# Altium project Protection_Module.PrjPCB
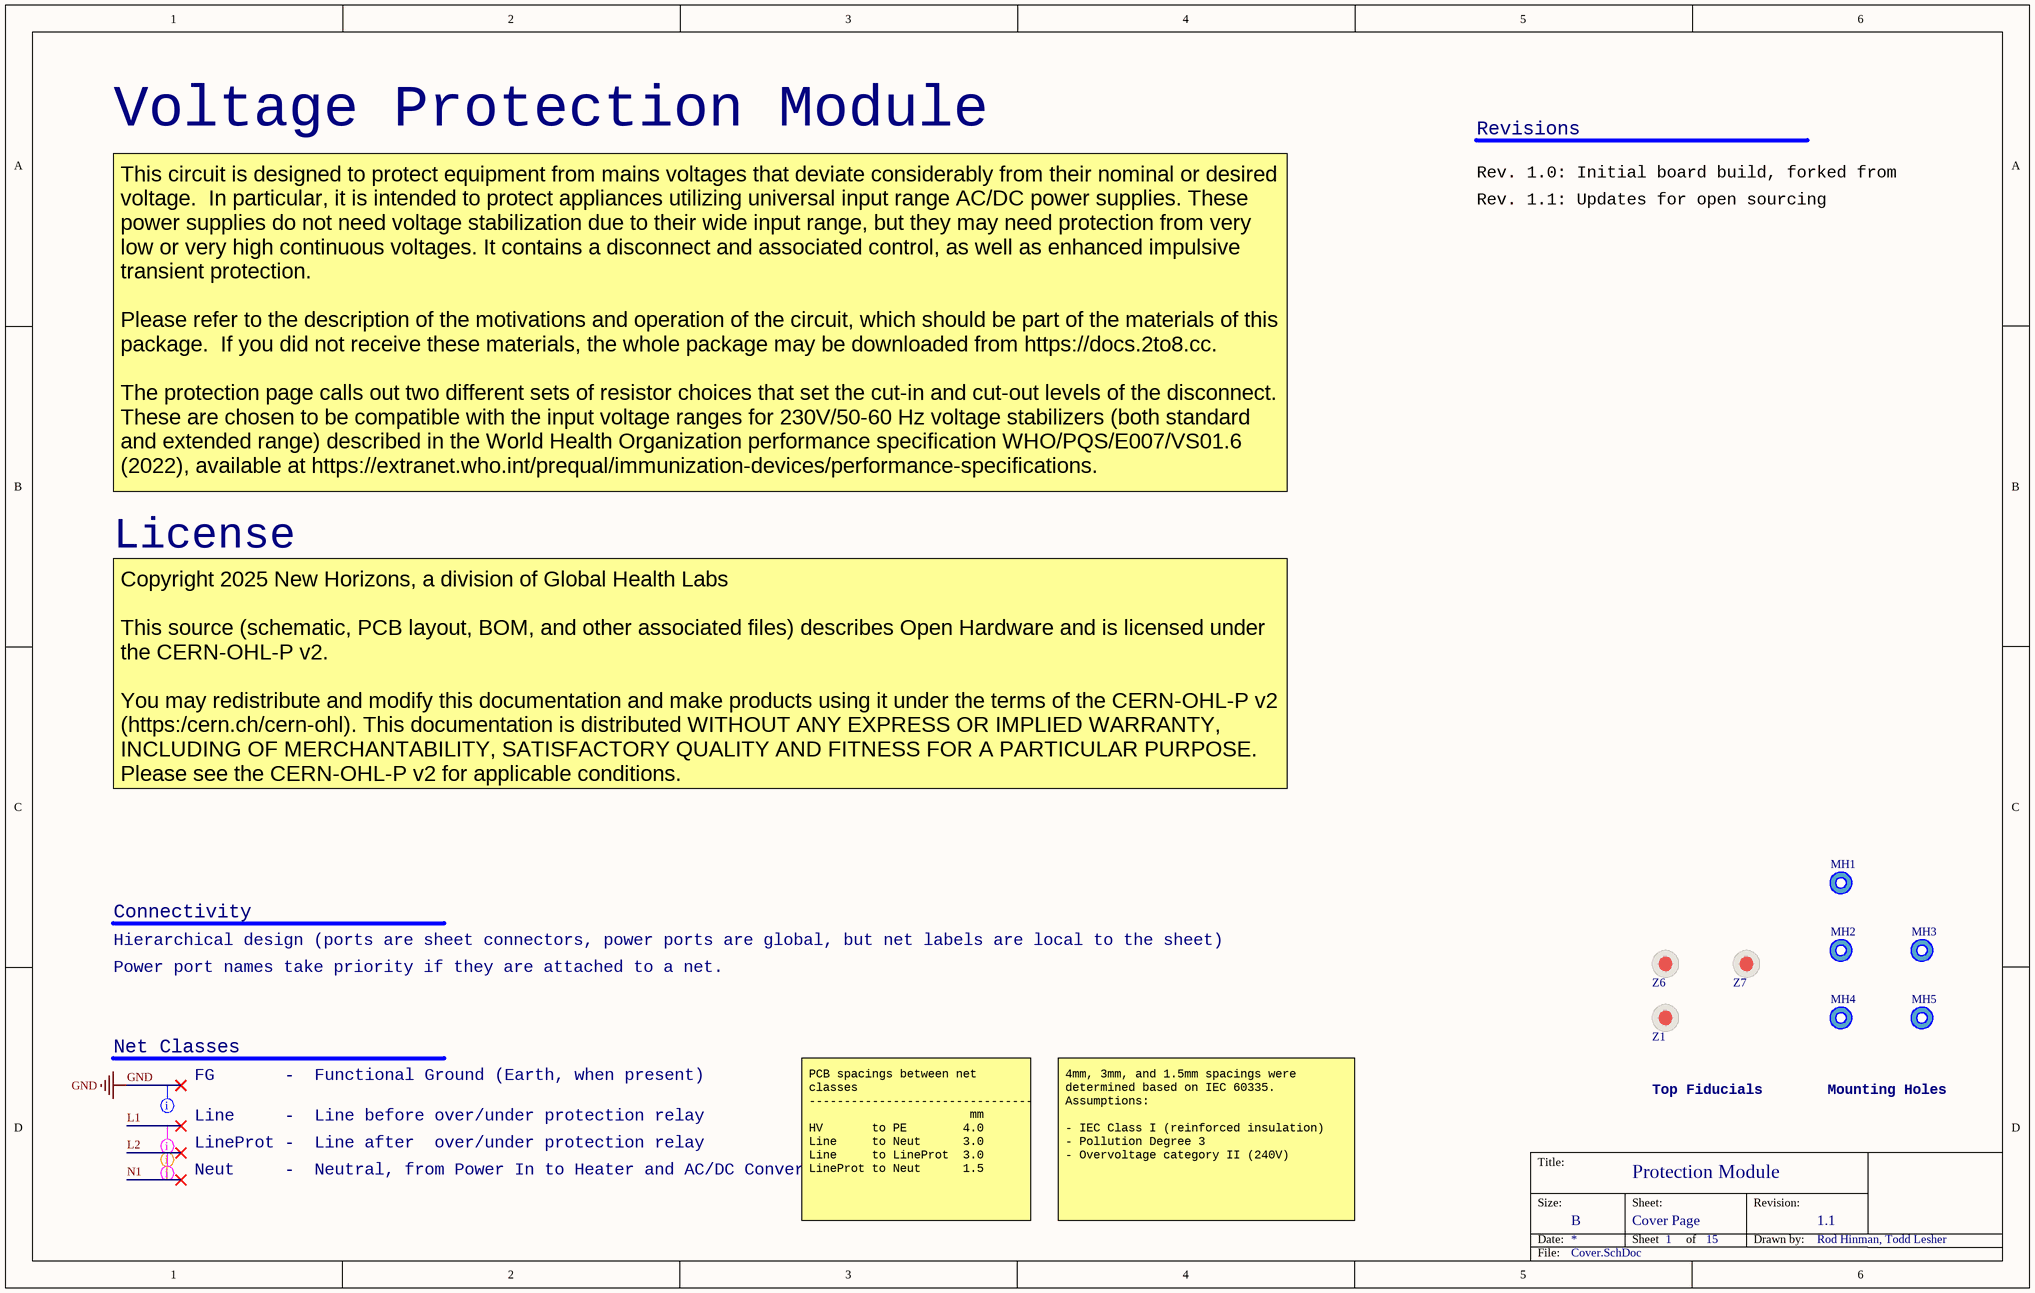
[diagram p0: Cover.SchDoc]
nhToday: 2025-05-24; nhSheetTotal: 3; nhProjRev: 1.1; nhProjName: Protection Module; nhEngPhone: 808-989-0977; nhEngName: Rod Hinman, Todd Lesher; nhEngEmail: rhinman@nhgh.org
3 sheets, 112 parts. Net scope: flat (ports and power ports of the same name join across sheets).
Board file: prot_mod.PcbDoc
Sheets:
  Cover.SchDoc
  PowerHV.SchDoc
  Protect.SchDoc

## Sheet Cover.SchDoc
size B; SheetNumber: 1; SheetTotal: 15; nhSheetName: Cover Page

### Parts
MH1  MOUNTING_HOLE_3MM_UNPLATED  [MOUNT_HOLE_3MM_NOCOPPER]  (value not drawn)  (no BOM)
MH2  MOUNTING_HOLE_3MM_UNPLATED  [MOUNT_HOLE_3MM_NOCOPPER]  (value not drawn)  (no BOM)
MH3  MOUNTING_HOLE_3MM_UNPLATED  [MOUNT_HOLE_3MM_NOCOPPER]  (value not drawn)  (no BOM)
MH4  MOUNTING_HOLE_3MM_UNPLATED  [MOUNT_HOLE_3MM_NOCOPPER]  (value not drawn)  (no BOM)
MH5  MOUNTING_HOLE_3MM_UNPLATED  [MOUNT_HOLE_3MM_NOCOPPER]  (value not drawn)  (no BOM)
Z1  FIDUCIAL_1_3  [FIDUCIAL_1_3_KEEPOUT]  (value not drawn)  (no BOM)
Z6  FIDUCIAL_1_3  [FIDUCIAL_1_3_KEEPOUT]  (value not drawn)  (no BOM)
Z7  FIDUCIAL_1_3  [FIDUCIAL_1_3_KEEPOUT]  (value not drawn)  (no BOM)

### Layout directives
net class Neut: N1
net class Line: L1
net class LineProt: L2
net class FG: GND

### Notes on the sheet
- Voltage Protection Module
- Revisions
- Rev. 1.0: Initial board build, forked from Protection-1
- Rev. 1.1: Updates for open sourcing
- This circuit is designed to protect equipment from mains voltages that deviate considerably from their nominal or desired voltage.  In particular, it is intended to protect appliances utilizing universal input range AC/DC power supplies. These power supplies do not need voltage stabilization due to their wide input range, but they may need protection from very low or very high continuous voltages. It contains a disconnect and associated control, as well as enhanced impulsive transient protection.
  Please refer to the description of the motivations and operation of the circuit, which should be part of the materials of this package.  If you did not receive these materials, the whole package may be downloaded from https://docs.2to8.cc.
  The protection page calls out two different sets of resistor choices that set the cut-in and cut-out levels of the disconnect.  These are chosen to be compatible with the input voltage ranges for 230V/50-60 Hz voltage stabilizers (both standard and extended range) described in the World Health Organization performance specification WHO/PQS/E007/VS01.6 (2022), available at https://extranet.who.int/prequal/immunization-devices/performance-specifications.
- License
- Copyright 2025 New Horizons, a division of Global Health Labs
  This source (schematic, PCB layout, BOM, and other associated files) describes Open Hardware and is licensed under the CERN-OHL-P v2.
  You may redistribute and modify this documentation and make products using it under the terms of the CERN-OHL-P v2 (https:/cern.ch/cern-ohl). This documentation is distributed WITHOUT ANY EXPRESS OR IMPLIED WARRANTY, INCLUDING OF MERCHANTABILITY, SATISFACTORY QUALITY AND FITNESS FOR A PARTICULAR PURPOSE. Please see the CERN-OHL-P v2 for applicable conditions.
- Hierarchical design (ports are sheet connectors, power ports are global, but net labels are local to the sheet)
- Power port names take priority if they are attached to a net.
- Connectivity
- Net Classes
- FG       -  Functional Ground (Earth, when present)
- Top Fiducials
- Mounting Holes
- Neut     -  Neutral, from Power In to Heater and AC/DC Converter
- Line     -  Line before over/under protection relay
- LineProt -  Line after  over/under protection relay
- PCB spacings between net classes
  --------------------------------
  mm
  HV       to PE        4.0
  Line     to Neut      3.0
  Line     to LineProt  3.0
  LineProt to Neut      1.5
- 4mm, 3mm, and 1.5mm spacings were determined based on IEC 60335.
  Assumptions:
  - IEC Class I (reinforced insulation)
  - Pollution Degree 3
  - Overvoltage category II (240V)

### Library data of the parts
MH1-MH5 = CMP-NOBOM-00004-1: Hole for M3 screw, unplated
Z1 Z6 Z7 = CMP-NOBOM-00000-1: Fiducial 1 mm copper, 3 mm solder mask, two footprint options.

## Sheet PowerHV.SchDoc
size B; SheetNumber: 2; SheetTotal: 15; nhSheetName: HV Power
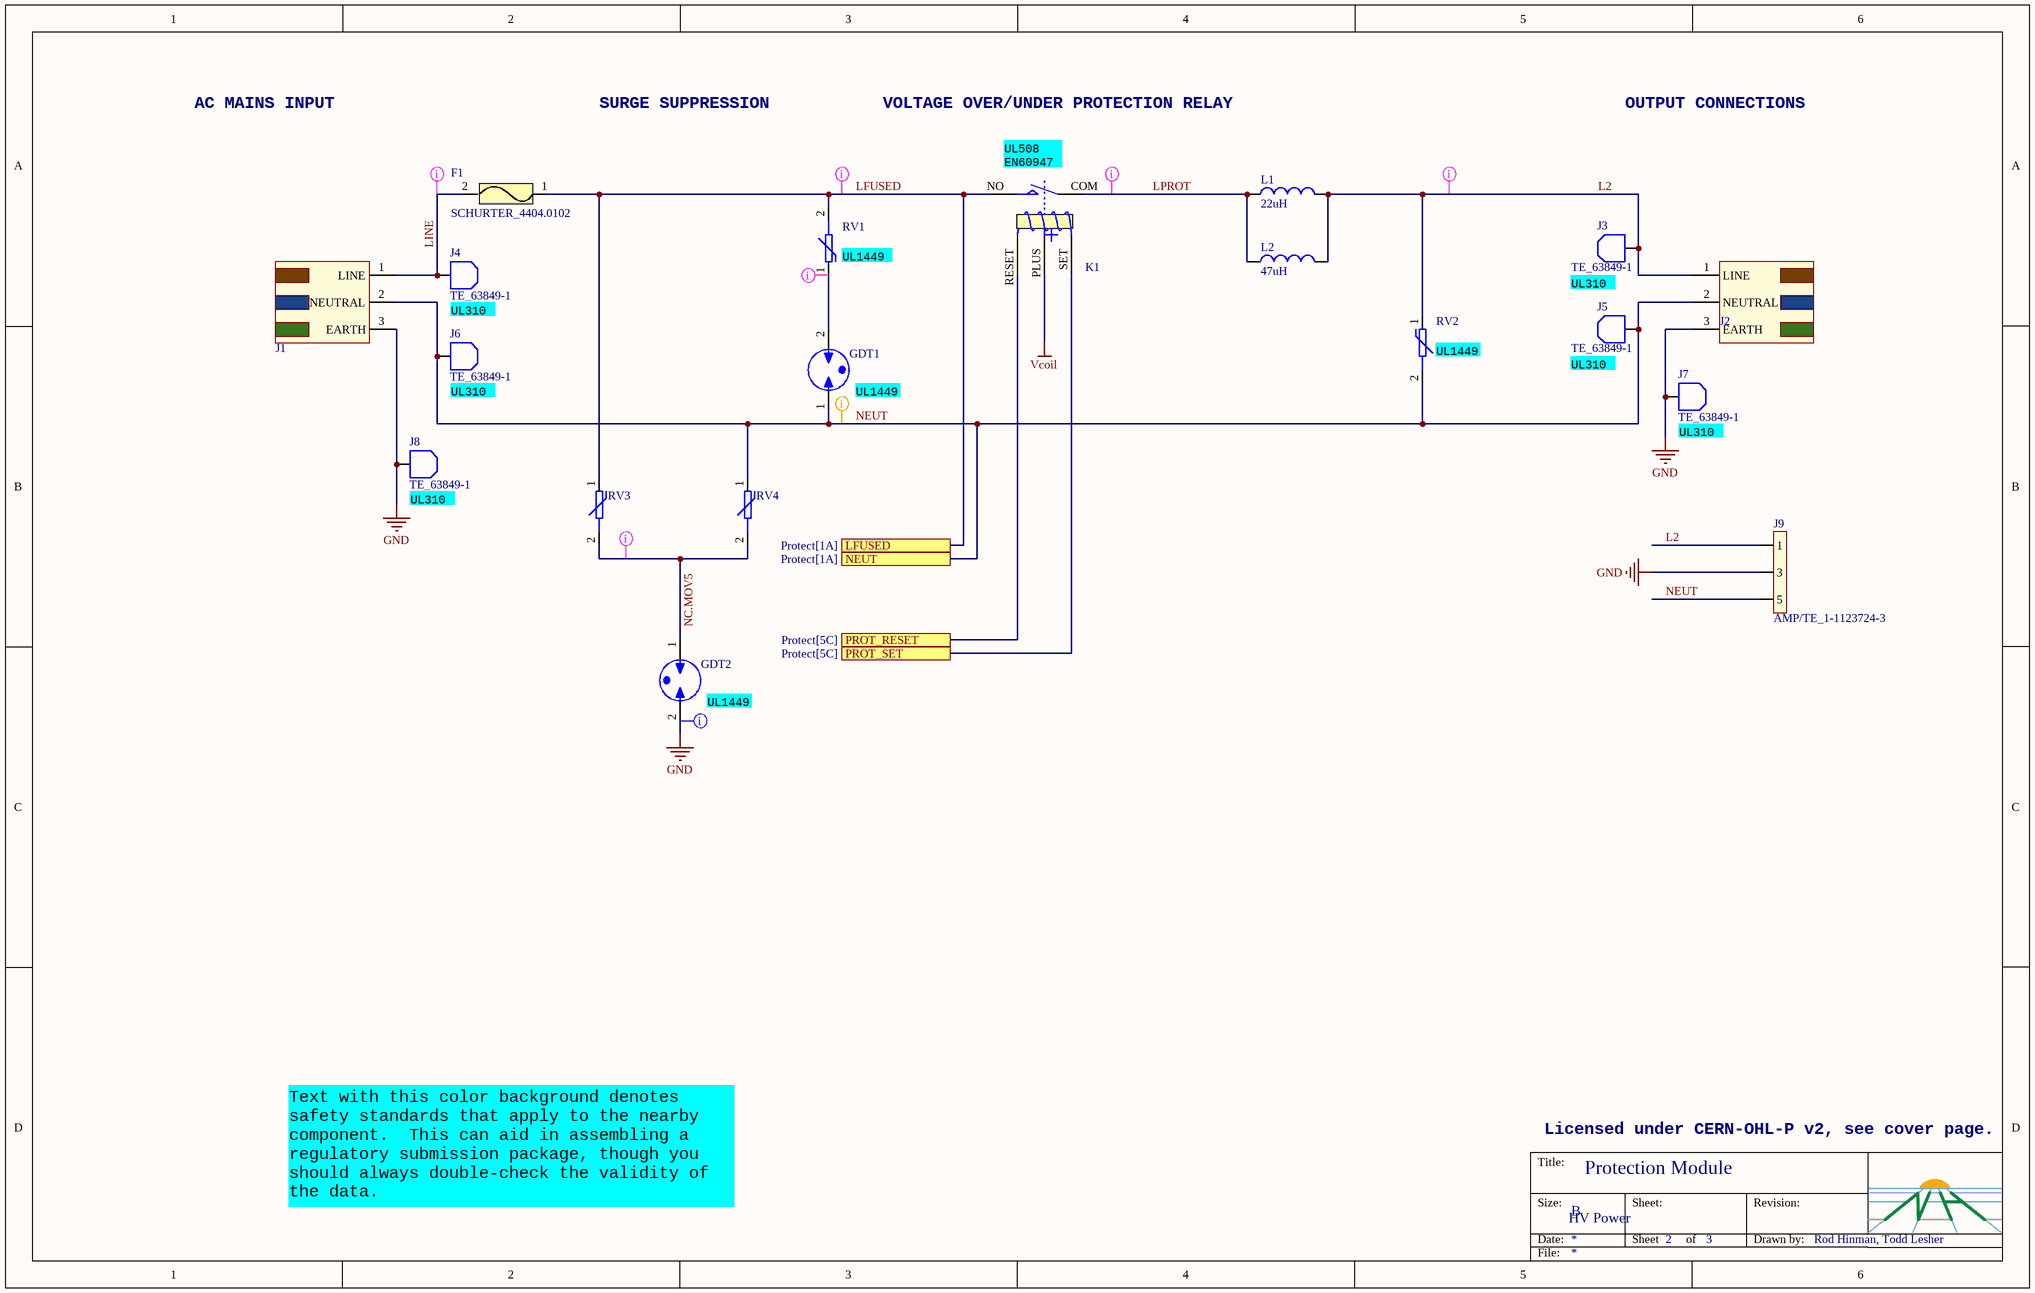
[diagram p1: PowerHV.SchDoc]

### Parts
F1  SCHURTER_4404.0102  [SCHURTER_T9-818]
GDT1  CG31.0L  [LITTELFUSE_CG3x]  (value not drawn)
GDT2  CG32.5L  [LITTELFUSE_CG3x]  (value not drawn)
J1  703W-00/54  [QUALTEK_703W-00/54]  (value not drawn)
J2  PX0675/PC  [BULGIN_PX0675/PC]  (value not drawn)
J3  TE_63849-1  [AMP_63849-1]
J4  TE_63849-1  [AMP_63849-1]
J5  TE_63849-1  [AMP_63849-1]
J6  TE_63849-1  [AMP_63849-1]
J7  TE_63849-1  [AMP_63849-1]
J8  TE_63849-1  [AMP_63849-1]
J9  AMP/TE_1-1123724-3  [AMP_1-1123724-3]
K1  TE_CONN_2-1415898-5  [TE_RT1_2COIL_LATCHING]  (value not drawn)
L1  value 22uH  [INDUCTOR-BOURNS_SRP1265CC]  (hidden comment: SRP1265CC-220M)
L2  value 47uH  [BELFUSE_HCTI_TOROIDAL_INDUCTOR]  (hidden comment: BELFUSE_HCTI-47-10.7)
RV1  TMOV20RP300E  [MOV_RAD7.5P5.5S_DISC_20X11.5]  (value not drawn)
RV2  TMOV20RP300E  [MOV_RAD7.5P5.5S_DISC_20X11.5]  (value not drawn)
RV3  TMOV20RP300E  [MOV_RAD7.5P5.5S_DISC_20X11.5]  (value not drawn)
RV4  TMOV20RP300E  [MOV_RAD7.5P5.5S_DISC_20X11.5]  (value not drawn)

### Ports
LFUSED (see Protect[1A]), NEUT (see Protect[1A]), PROT_RESET (see Protect[5C]), PROT_SET (see Protect[5C])

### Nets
GND: GDT2.2 J1.3(EARTH) J2.3(EARTH) J7.1 J8.1 J9.3
Vcoil: K1.PLUS
L2: J2.1(LINE) J3.1 J9.1 L1.2 L2.2 RV2.1
LFUSED: F1.1 K1.NO RV1.2 RV3.1 ; port LFUSED
LINE: F1.2 J1.1(LINE) J4.1
LPROT: K1.COM L1.1 L2.1
NC.MOV5: GDT2.1 RV3.2 RV4.2
NEUT: GDT1.1 J1.2(NEUTRAL) J2.2(NEUTRAL) J5.1 J6.1 J9.5 RV2.2 RV4.1 ; port NEUT
PROT_RESET: K1.RESET ; port PROT_RESET
PROT_SET: K1.SET ; port PROT_SET
NetGDT1_2: GDT1.2 RV1.1

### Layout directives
net class Line: LFUSED, LINE, NC.MOV5, NetGDT1_2
net class LineProt: L2, LPROT
net class Neut: NEUT
net class FG: GND

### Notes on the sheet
- AC MAINS INPUT
- SURGE SUPPRESSION
- VOLTAGE OVER/UNDER PROTECTION RELAY
- (near K1) UL508
  EN60947
- OUTPUT CONNECTIONS
- (near RV1) UL1449
- UL310
- (near RV2) UL1449
- (near J5) UL310
- (near J6) UL310
- (near GDT1) UL1449
- (near J7) UL310
- (near J8) UL310
- (near GDT2) UL1449
- Licensed under CERN-OHL-P v2, see cover page.
- Text with this color background denotes safety standards that apply to the nearby component.  This can aid in assembling a regulatory submission package, though you should always double-check the validity of the data.

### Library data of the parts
F1 = CMP-FUSE-00000-2: Circuit Breaker Thermal 1P 240VAC/48DC 10A PCB Mnt-Thru-Hole Push Reset QC Term.; Voltage Rating (AC): 240V; Voltage Rating (DC): 48V
GDT1 = CMP-PROT-00004-1: CG3 Series - Two Terminal High Voltage Gas Plasma Arresters, 1000V, 10kA, plug in, RoHS; Breakdown Voltage: 1.0kV
GDT2 = CMP-PROT-00003-2: Arrestor; 2500 V (min.) (breakdown); Rugged Ceramic-metal Package; 1 Pf (max.); Breakdown Voltage: 2.5kV
J1 = CMP-CONN-00000-2: Conn Electrical Power Inlet Right Angled Pin Cont 3 Cond 3 Poles Solder 250V
J2 = CMP-CONN-00001-2: Conn Electrical Power Outlet Right Angled Pin Cont 3 Cond 3 Poles Solder 250V
J3-J8 = CMP-CONN-00004-1: Quick Disconnect Terminal 12-24AWG Brass Tab 14.02mm Tin Over Copper/Tin Over Nickel Bag; Tab Width: 6.35mm
J9 = CMP-CONN-00006-1: Conn Power HDR 5 POS 3.96mm Solder ST Thru-Hole 5 Terminal 1 Port; Voltage Rating: 250V
K1 = CMP-RELAY-00000-2: Electromechanical Relay SPST-NO 16A 12VDC 240Ohm Through Hole; Contact Voltage Rating (AC): 250V; Coil Power: 600mW; Throw Configuration: SPST
L1 = CMP-IND-00003-1: Inductor Power Shielded Wirewound 22uH 20% 100KHz 20Q-Factor Carbonyl Powder 10A 0.037Ohm DCR
L2 = CMP-IND-00005-2: 47 µH Shielded Toroidal Inductor 10.7 A 16mOhm Max Radial, Vertical (Open); Tolerance: 15%; DC Resistance (DCR): 16mR; Core Material: Ferrite; Current Rating: 10.7A
RV1 RV3 RV4 = CMP-PROT-00005-2: Thermally Protected Varistor 300 V RMS 775 V Clamp 10000 A 800 pF Radial Lead; Voltage Rating (AC): 300V; Varistor Voltage: 517V
RV2 = CMP-PROT-00005-2: Thermally Protected Varistor 300 V RMS 775 V Clamp 10000 A 800 pF Radial Lead; Varistor Voltage: 517V; Voltage Rating (AC): 300V

## Sheet Protect.SchDoc
size B; SheetNumber: 4; SheetTotal: 15; nhSheetName: Protect
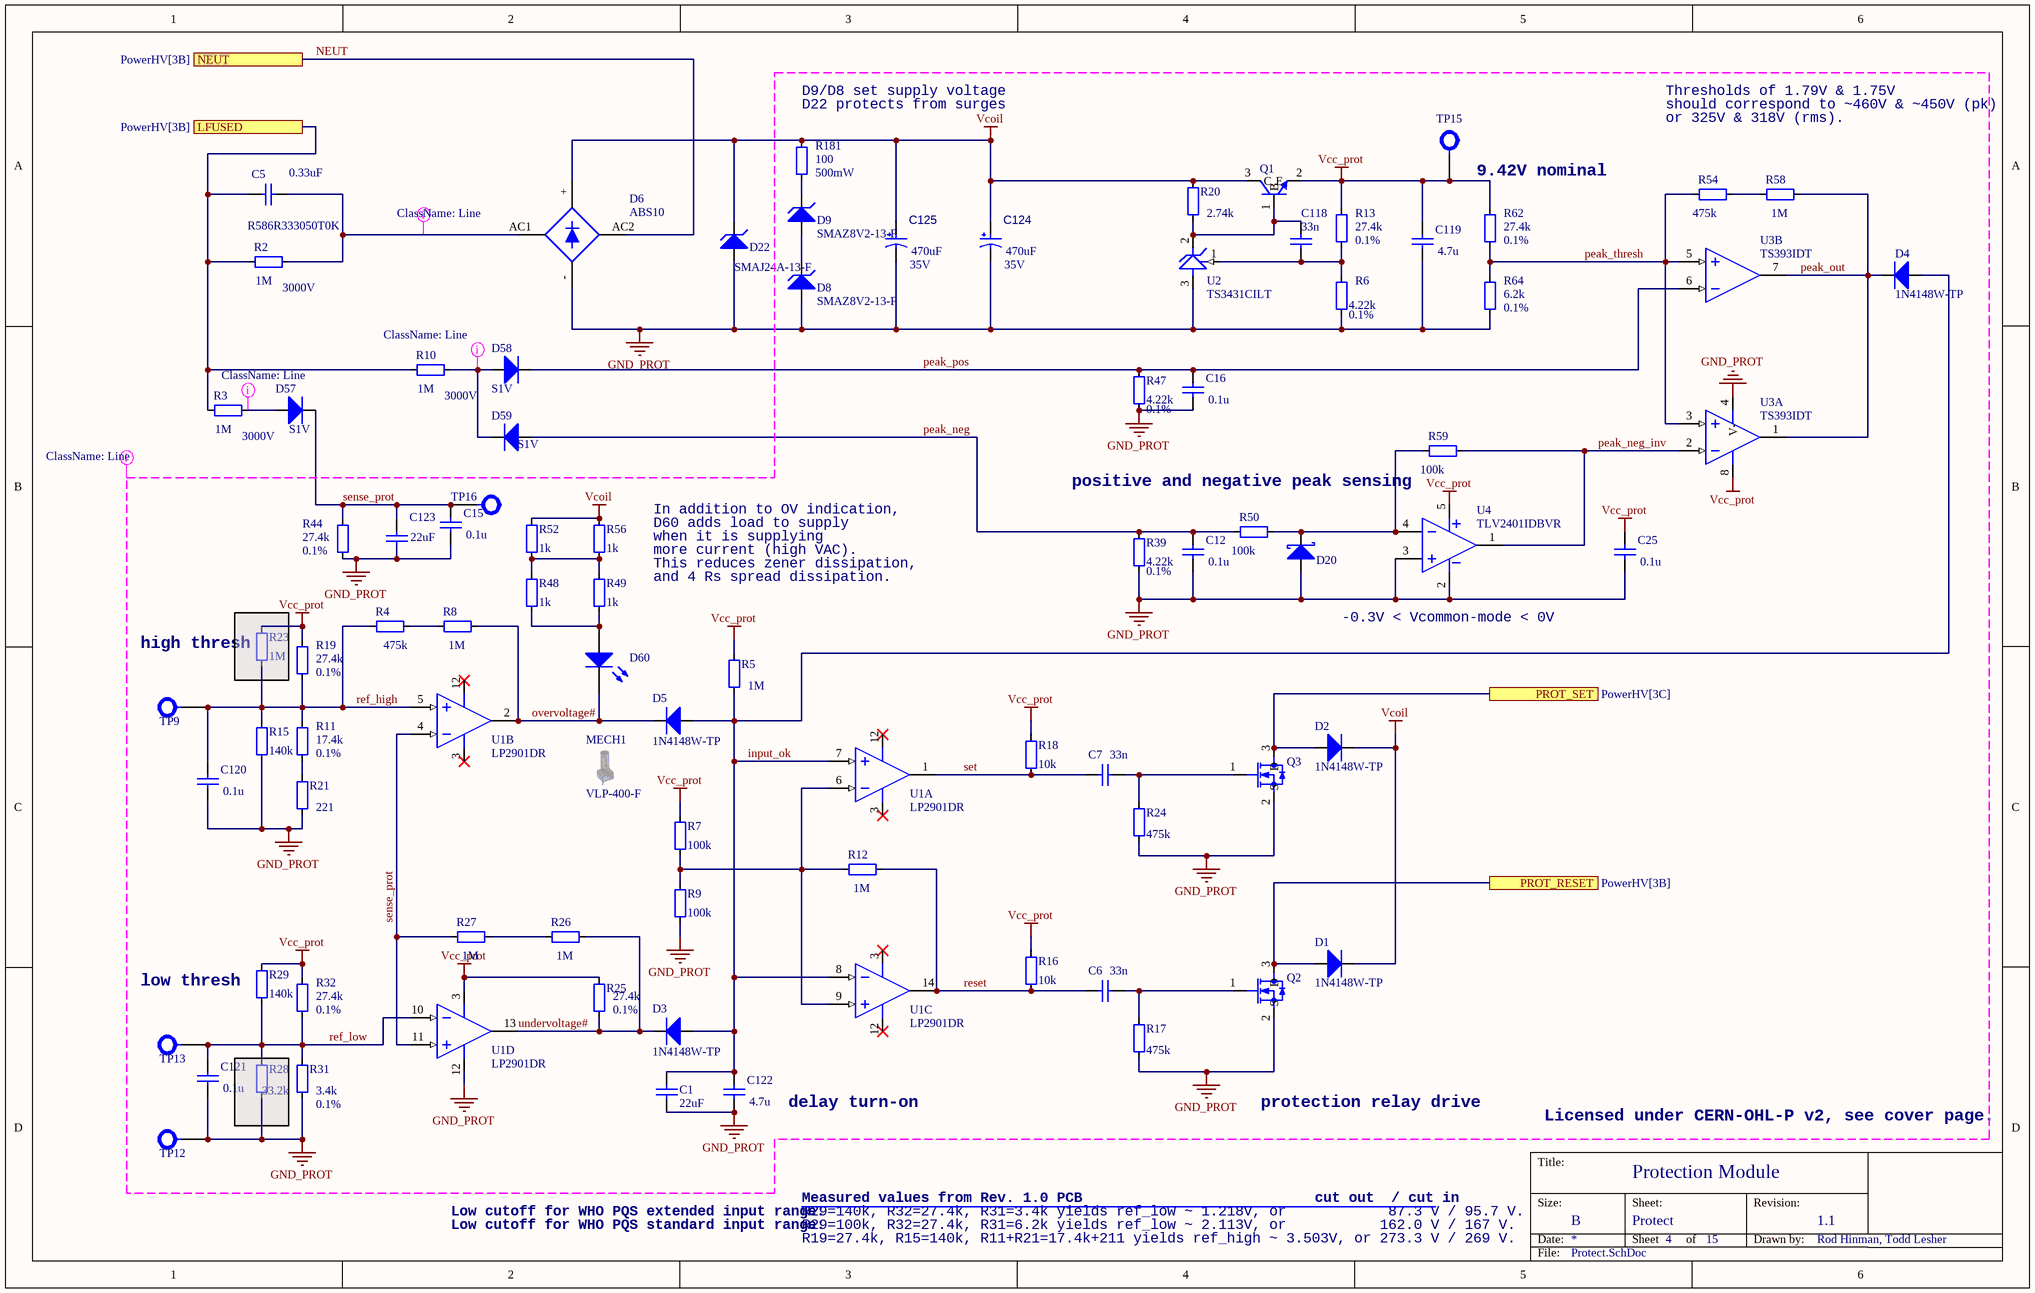
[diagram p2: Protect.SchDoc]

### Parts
C1  value 22uF  [CAPC2012X135,0805,]  (hidden comment: CL21A226MOCLRNC)
C5  R586R333050T0K  value 0.33uF  [CAP_RAD28P3213X22]
C6  value 33n  [CAPC1608X09N[0603]]  (hidden comment: CL10B333KB8NNNC)
C7  value 33n  [CAPC1608X09N[0603]]  (hidden comment: CL10B333KB8NNNC)
C12  value 0.1u  [CAPC1608X09N[0603]]  (hidden comment: CL10B104KB8NNNL)
C15  value 0.1u  [CAPC1608X09N[0603]]  (hidden comment: CL10B104KB8NNNL)
C16  value 0.1u  [CAPC1608X09N[0603]]  (hidden comment: CL10B104KB8NNNL)
C25  value 0.1u  [CAPC1608X09N[0603]]  (hidden comment: CL10B104KB8NNNL)
C118  value 33n  [CAPC1608X09N[0603]]  (hidden comment: CL10B333KB8NNNC)
C119  value 4.7u  [CAPC1608X09N[0603]]  (hidden comment: CL10A475KA8NQNC)
C120  value 0.1u  [CAPC1608X09N[0603]]  (hidden comment: CL10B104KB8NNNL)
C121  value 0.1u  [CAPC1608X09N[0603]]  (hidden comment: CL10B104KB8NNNL)
C122  value 4.7u  [CAPC1608X09N[0603]]  (hidden comment: CL10A475KA8NQNC)
C123  value 22uF  [CAPC2012X135,0805,]  (hidden comment: CL21A226MOCLRNC)
C124  value 470uF  Voltage Rating (DC): 35V  [CAP_RAD5P_CYL_10X20]  (hidden comment: ESH477M035AH3AA)
C125  value 470uF  Voltage Rating (DC): 35V  [CAP_RAD5P_CYL_10X20]  (hidden comment: ESH477M035AH3AA)
D1  1N4148W-TP  [SOD-123]
D2  1N4148W-TP  [SOD-123]
D3  1N4148W-TP  [SOD-123]
D4  1N4148W-TP  [SOD-123]
D5  1N4148W-TP  [SOD-123]
D6  ABS10  [SOP400P640X170-4N_BRIDGE]
D8  SMAZ8V2-13-F  [DO-214AC]
D9  SMAZ8V2-13-F  [DO-214AC]
D20  MBR130T1G  [SOD-123]  (value not drawn)
D22  SMAJ24A-13-F  [DO-214AC]
D57  S1V  [DO-214AC]
D58  S1V  [DO-214AC]
D59  S1V  [DO-214AC]
D60  APTR3216SURCK  [LEDC3216X08NREDBOT,1206,]  (value not drawn)
MECH1  VLP-400-F  [BIVAR_VLP-400-F]
Q1  BCV72,215  [SOT95P275X125-3N]  (value not drawn)
Q2  IRLML6346TRPBF  [SOT95P275X125-3N]  (value not drawn)
Q3  IRLML6346TRPBF  [SOT95P275X125-3N]  (value not drawn)
R2  value 1M  Voltage Rating: 3000V  [RESC6534X70,2512,]  (hidden comment: CHV2512-FX-1004ELF)
R3  value 1M  Voltage Rating: 3000V  [RESC6534X70,2512,]  (hidden comment: CHV2512-FX-1004ELF)
R4  value 475k  [RESC1608X05AN[0603]]  (hidden comment: ERJ-3EKF4753V)
R5  value 1M  [RESC1608X05AN[0603]]  (hidden comment: ERJ-3EKF1004V)
R6  value 4.22k  Tolerance: 0.1%  [RESC1608X05AN[0603]]  (hidden comment: ERA-3AEB4221V)
R7  value 100k  [RESC1608X05AN[0603]]  (hidden comment: ERJ-3EKF1003V)
R8  value 1M  [RESC1608X05AN[0603]]  (hidden comment: ERJ-3EKF1004V)
R9  value 100k  [RESC1608X05AN[0603]]  (hidden comment: ERJ-3EKF1003V)
R10  value 1M  Voltage Rating: 3000V  [RESC6534X70,2512,]  (hidden comment: CHV2512-FX-1004ELF)
R11  value 17.4k  Tolerance: 0.1%  [RESC1608X05AN[0603]]  (hidden comment: ERA-3AEB1742V)
R12  value 1M  [RESC1608X05AN[0603]]  (hidden comment: ERJ-3EKF1004V)
R13  value 27.4k  Tolerance: 0.1%  [RESC1608X05AN[0603]]  (hidden comment: ERA-3AEB2742V)
R15  value 140k  [RESC1608X05AN[0603]]  (hidden comment: RMCF0603FT140K)
R16  value 10k  [RESC1608X05AN[0603]]  (hidden comment: RMCF0603FT10K0)
R17  value 475k  [RESC1608X05AN[0603]]  (hidden comment: ERJ-3EKF4753V)
R18  value 10k  [RESC1608X05AN[0603]]  (hidden comment: RMCF0603FT10K0)
R19  value 27.4k  Tolerance: 0.1%  [RESC1608X05AN[0603]]  (hidden comment: ERA-3AEB2742V)
R20  value 2.74k  [RESC1608X05AN[0603]]  (hidden comment: RMCF0603FT2K74)
R21  value 221  [RESC1608X05AN[0603]]  (hidden comment: ERJ-3EKF2210V)
R23  value 1M  [RESC1608X05AN[0603]]  (hidden comment: ERJ-3EKF1004V)
R24  value 475k  [RESC1608X05AN[0603]]  (hidden comment: ERJ-3EKF4753V)
R25  value 27.4k  Tolerance: 0.1%  [RESC1608X05AN[0603]]  (hidden comment: ERA-3AEB2742V)
R26  value 1M  [RESC1608X05AN[0603]]  (hidden comment: ERJ-3EKF1004V)
R27  value 1M  [RESC1608X05AN[0603]]  (hidden comment: ERJ-3EKF1004V)
R28  value 33.2k  [RESC1608X05AN[0603]]  (hidden comment: ERJ-3EKF3322V)
R29  value 140k  [RESC1608X05AN[0603]]  (hidden comment: RMCF0603FT140K)
R31  value 3.4k  Tolerance: 0.1%  [RESC1608X05AN[0603]]  (hidden comment: ERA-3AEB3401V)
R32  value 27.4k  Tolerance: 0.1%  [RESC1608X05AN[0603]]  (hidden comment: ERA-3AEB2742V)
R39  value 4.22k  Tolerance: 0.1%  [RESC1608X05AN[0603]]  (hidden comment: ERA-3AEB4221V)
R44  value 27.4k  Tolerance: 0.1%  [RESC1608X05AN[0603]]  (hidden comment: ERA-3AEB2742V)
R47  value 4.22k  Tolerance: 0.1%  [RESC1608X05AN[0603]]  (hidden comment: ERA-3AEB4221V)
R48  value 1k  [RESC1608X05AN[0603]]  (hidden comment: ERJ-3EKF1001V)
R49  value 1k  [RESC1608X05AN[0603]]  (hidden comment: ERJ-3EKF1001V)
R50  value 100k  [RESC1608X05AN[0603]]  (hidden comment: ERJ-3EKF1003V)
R52  value 1k  [RESC1608X05AN[0603]]  (hidden comment: ERJ-3EKF1001V)
R54  value 475k  [RESC1608X05AN[0603]]  (hidden comment: ERJ-3EKF4753V)
R56  value 1k  [RESC1608X05AN[0603]]  (hidden comment: ERJ-3EKF1001V)
R58  value 1M  [RESC1608X05AN[0603]]  (hidden comment: ERJ-3EKF1004V)
R59  value 100k  [RESC1608X05AN[0603]]  (hidden comment: ERJ-3EKF1003V)
R62  value 27.4k  Tolerance: 0.1%  [RESC1608X05AN[0603]]  (hidden comment: ERA-3AEB2742V)
R64  value 6.2k  Tolerance: 0.1%  [RESC1608X05AN[0603]]  (hidden comment: ERA-3AEB622V)
R181  value 100  Power: 500mW  [RESC2012X06N,0805,]  (hidden comment: ERJ-P06F1000V)
TP9  TP TH  0.78mm  [TP_TH078H127P]  (value not drawn)  (no BOM)
TP12  TP TH  0.78mm  [TP_TH078H127P]  (value not drawn)  (no BOM)
TP13  TP TH  0.78mm  [TP_TH078H127P]  (value not drawn)  (no BOM)
TP15  TP TH  0.78mm  [TP_TH078H127P]  (value not drawn)  (no BOM)
TP16  TP TH  0.78mm  [TP_TH078H127P]  (value not drawn)  (no BOM)
U1  LP2901DR  [SOIC127P600X175-14N]  (parts A,B,C,D of 4)
U2  TS3431CILT  [SOT95P275X125-3N]
U3  TS393IDT  [SOIC127P600X175-8N]  (parts A,B of 2)
U4  TLV2401IDBVR  [SOT95P280X145-5N]

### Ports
LFUSED (see PowerHV[3B]), NEUT (see PowerHV[3B]), PROT_RESET (see PowerHV[3B]), PROT_SET (see PowerHV[3C])

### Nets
GND_PROT: C1.2 C12.2 C15.2 C16.2 C25.2 C119.2 C120.2 C121.2 C122.2 C123.2 C124.- C125.- D6.- D8.A D20.A D22.A Q2.2(S) Q3.2(S) R6.2 R9.2 R15.2 R17.1 R21.2 R24.1 R28.2 R31.2 R39.2 R44.2 R47.2 R64.2 TP12.1 U1.12(V-) U2.3(A) U3.4(V-) U4.2(-Vs) U4.3(+IN)
Vcc_prot: C25.1 C119.1 Q1.2(E) R5.1 R7.1 R13.1 R16.1 R18.1 R19.1 R23.1 R25.2 R29.1 R32.1 R62.1 TP15.1 U1.3(V+) U3.8(V+) U4.5(+Vs)
Vcoil: C124.+ C125.+ D1.K D2.K D6.+ D22.K Q1.3(C) R20.2 R52.1 R56.1 R181.1
input_ok: C1.1 C122.1 D3.A D4.A D5.A R5.2 U1.7(IN1+) U1.8(IN3-)
LFUSED: C5.1 R2.1 R3.1 R10.1 ; port LFUSED
NEUT: D6.AC2 ; port NEUT
overvoltage#: D5.K D60.K R8.2 U1.2(OUT2)
peak_neg: C12.1 D59.A R39.1 R50.1
peak_neg_inv: R59.2 U3.2(IN1-) U4.1(OUT)
peak_out: D4.K R58.2 U3.1(OUT1) U3.7(OUT2)
peak_pos: C16.1 D58.K R47.1 U3.6(IN2-)
peak_thresh: R54.2 R62.2 R64.1 U3.3(IN1+) U3.5(IN2+)
PROT_RESET: D1.A Q2.3(D) ; port PROT_RESET
PROT_SET: D2.A Q3.3(D) ; port PROT_SET
ref_high: C120.1 R4.2 R11.2 R15.1 R19.2 R23.2 TP9.1 U1.5(IN2+)
ref_low: C121.1 R28.1 R29.2 R31.1 R32.2 TP13.1 U1.10(IN4-)
reset: C6.1 R12.2 R16.2 U1.14(OUT3)
sense_prot: C15.1 C123.1 D57.K R27.1 R44.1 TP16.1 U1.4(IN2-) U1.11(IN4+)
set: C7.1 R18.2 U1.1(OUT1)
undervoltage#: D3.K R25.1 R26.2 U1.13(OUT4)
NetC5_2: C5.2 D6.AC1 R2.2
NetC6_2: C6.2 Q2.1(G) R17.2
NetC7_2: C7.2 Q3.1(G) R24.2
NetC118_1: C118.1 Q1.1(B) R20.1 U2.2(K)
NetC118_2: C118.2 R6.1 R13.2 U2.1(VREF)
NetD8_K: D8.K D9.A
NetD9_K: D9.K R181.2
NetD20_K: D20.K R50.2 R59.1 U4.4(-IN)
NetD57_A: D57.A R3.2
NetD58_A: D58.A D59.K R10.2
NetD60_A: D60.A R48.2 R49.2
NetR4_1: R4.1 R8.1
NetR7_2: R7.2 R9.1 R12.1 U1.6(IN1-) U1.9(IN3+)
NetR11_1: R11.1 R21.1
NetR26_1: R26.1 R27.2
NetR48_1: R48.1 R49.1 R52.2 R56.2
NetR54_1: R54.1 R58.1

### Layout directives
net class Line: GND_PROT, input_ok, NetC5_2, NetD57_A, NetD58_A, overvoltage#, peak_neg, peak_neg_inv, peak_out, peak_pos, peak_thresh, ref_high, ref_low, reset, sense_prot, set, undervoltage#, Vcc_prot, Vcoil

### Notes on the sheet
- (near R181) D9/D8 set supply voltage
- Thresholds of 1.79V & 1.75V
- (near R181) D22 protects from surges
- should correspond to ~460V & ~450V (pk)
- or 325V & 318V (rms).
- 9.42V nominal
- positive and negative peak sensing
- D60 adds load to supply
- when it is supplying
- more current (high VAC).
- This reduces zener dissipation,
- In addition to OV indication,
- and 4 Rs spread dissipation.
- (near U4) -0.3V < Vcommon-mode < 0V
- (near R23) high thresh
- low thresh
- delay turn-on
- protection relay drive
- Licensed under CERN-OHL-P v2, see cover page.
- Low cutoff for WHO PQS extended input range:
- Low cutoff for WHO PQS standard input range:
- R29=140k, R32=27.4k, R31=3.4k yields ref_low ~ 1.218V, or            87.3 V / 95.7 V.
- R19=27.4k, R15=140k, R11+R21=17.4k+211 yields ref_high ~ 3.503V, or 273.3 V / 269 V.
- Measured values from Rev. 1.0 PCB
- R29=100k, R32=27.4k, R31=6.2k yields ref_low ~ 2.113V, or           162.0 V / 167 V.
- cut out  / cut in

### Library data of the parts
C1 C123 = CMP-CAP-00014-1: Multilayer Ceramic Capacitor, 22 uF, 16 V, ± 20%, X5R, 0805 [2012 Metric]; Voltage: 16V
C5 = CMP-CAP-00013-2: CAP FILM 600VAC(X1) 0.33 UF 10%
C6 C7 C118 = CMP-CAP-00006-2: Multilayer Ceramic Capacitor, 0.033 uF, 50 V, ± 10%, X7R, 0603 [1608 Metric]; Voltage Rating: 50V
C12 C15 C16 C25 C120 C121 = CMP-CAP-00002-4: Multilayer Ceramic Capacitor, 0.1 uF, 50 V, ± 10%, X7R, 0603 [1608 Metric]; Voltage Rating: 50V; Material: 4241
C119 C122 = CMP-CAP-00007-2: Multilayer Ceramic Capacitor, 4.7 uF, 25 V, ± 10%, X5R, 0603 [1608 Metric]; Voltage Rating: 25V; Dielectric: X7R
C124 C125 = CMP-CAP-00011-2: Capacitor; Al Electrolytic; Cap 470 uF; Tol 20%; Vol-Rtg 35 VDC; Radial; 10x17 mm; Dissipation Factor: 0.14%; Life (Hours): 2000Hour
D1-D5 = CMP-DIO-00000-3: Rectifier Diode Switching 100V 0.3A 4ns 2-Pin SOD-123 T/R / DIODE GEN PURP 100V 150MA SOD123; Forward Voltage: 1V; Power Dissipation: 400mW
D6 = CMP-DIO-00006-2: Bridge Rectifier Abs/Sopa-4 T&r 5K Rohs Compliant: Yes
D8 D9 = CMP-DIO-00003-3: DIODE ZENER 8.2V 1W SMA; Reverse Recovery Time: 1.8us; Forward Current: 1A; Forward Voltage: 1.2V
D20 = CMP-DIO-00001-3: DIODE SCHOTTKY 30V 1A SOD123 / Rectifier Diode Schottky 30V 1A 2-Pin SOD-123 T/R; Power Dissipation: 400mW; Reverse Recovery Time: 4ns; Forward Voltage: 470mV
D22 = CMP-DIO-00004-3: SMAJ24A Series 400 W 24 V Surface Mount Uni-Directional TVS Diode - DO-214AC; Forward Current: 1A; Power Dissipation: 400W; Forward Voltage: 1.2V; Reverse Recovery Time: 1.8us; Voltage Rating (DC): 24V
D57-D59 = CMP-DIO-00007-2: Diode Rectifier 2000V 1A 2-Pin DO-214AC T/R; Reverse Recovery Time: 2.5us; Forward Voltage: 1V; Voltage Rating (DC): 2kV; Power Dissipation: 1.4W
D60 = CMP-LED-00004-1: Red 3.2 x 1.6 x 1.05 mm (1206) 120º Water Clear 150 mcd 1.95 V Chip LED Lamp SMT; Forward Voltage: 1.95V; Forward Current: 20mA; Viewing Angle: 120°
MECH1 = CMP-LED-00003-5: Light Pipe, Rigid, Vertical, Board Mount, SMD LED, .400 in., Flat Face
Q1 = CMP-BJT-00000-1: BCV72 Series 60 V 100 mA 250 mW NPN SMT General Purpose Transistor - SOT-23; Collector Emitter Voltage (VCEO): 60V; Collector Base Voltage (VCBO): 80V; Frequency: 100MHz; Max Collector Current: 100mA
Q2 Q3 = CMP-FET-00000-1: MOSFET Transistor, N Channel, 3.4 A, 30 V, 0.046 ohm, 4.5 V, 800 mV; Drain to Source Voltage (Vdss): 30V; Continuous Drain Current (ID): 3.4A; Drain to Source Resistance: 46mR
R2 R3 R10 = CMP-RES-00067-2: SMD Chip Resistor, 1 MOhm, ± 1%, 1 W, 2512 [6332 Metric], Thick Film, High Voltage; Max Power Dissipation: 1.0W; Temperature Coefficient: 100ppm/°C
R4 R17 R24 R54 = CMP-RES-00002-1: SMD Chip Resistor, 475 kOhm, ± 1%, 100 mW, 0603 [1608 Metric], Thick Film, Precision; Max Power Dissipation: 100mW; Voltage Rating: 75V; Temperature Coefficient: 100ppm/°C
R5 R8 R12 R23 R26 R27 R58 = CMP-RES-00000-4: Res Thick Film 0603 1M Ohm 1% 1/10W ±100ppm/°C Molded SMD Punched Carrier T/R; Voltage Rating (DC): 75V; Max Power Dissipation: 100mW
R6 R39 R47 = CMP-RES-00064-1: Res Thin Film 0603 4.22K Ohm 0.1% 1/10W ±25ppm/°C Molded SMD SMD Punched Carrier T/R; Max Power Dissipation: 100mW; Voltage Rating: 75V
R7 R9 R50 R59 = CMP-RES-00004-3: Resistor Thick Film 0603 100K Ohm 1% 1/10W 100ppm/C Molded SMD Punched Carrier T/R; Max Power Dissipation: 100mW; Voltage Rating (DC): 75V; Temperature Coefficient: 100ppm/°C
R11 = CMP-RES-00063-1: Res Thin Film 0603 17.4K Ohm 0.1% 0.1W(1/10W) ±25ppm/C Pad SMD Automotive T/R; Max Power Dissipation: 100mW; Voltage Rating (DC): 75V; Temperature Coefficient: 25ppm/°C
R13 R19 R25 R32 R44 R62 = CMP-RES-00062-1: Res Thin Film 0603 27.4K Ohm 0.1% 0.1W(1/10W) ±25ppm/C Pad SMD Automotive T/R; Power: 100mW; Temperature Coefficient: 25ppm/°C; Voltage Rating: 75V
R15 R29 = CMP-RES-00060-1: Res Thick Film 0603 140K Ohm 1% 1/10W ±100ppm/°C Molded SMD SMD Paper T/R; Voltage Rating (DC): 75V; Power: 100mW
R16 R18 = CMP-RES-00016-2: Res Thick Film 0603 10K Ohm 1% 1/10W ±100ppm/°C Molded SMD SMD Paper T/R; Max Power Dissipation: 100mW; Voltage Rating (DC): 75V
R20 = CMP-RES-00061-1: Res Thick Film 0603 2.74K Ohm 1% 1/10W ±100ppm/°C Molded SMD SMD Paper T/R; Voltage Rating: 75V; Power Rating: 100mW
R21 = CMP-RES-00012-1: SMD Chip Resistor, 221 Ohm, ± 1%, 100 mW, 0603 [1608 Metric], Thick Film, Precision; Temperature Coefficient: 100ppm/°C; Voltage Rating: 75V; Power Rating: 100mW
R28 = CMP-RES-00008-1: Res Thick Film 0603 33.2K Ohm 1% 1/10W +/-100ppm/ßC Molded SMD Punched Carrier T/R; Voltage Rating: 50V; Power: 100mW; Temperature Coefficient: 100ppm/°C
R31 = CMP-RES-00065-1: Res Thin Film 0603 3.4K Ohm 0.1% 0.1W(1/10W) ±25ppm/C Pad SMD Automotive T/R; Power: 100mW; Temperature Coefficient: 25ppm/°C; Voltage Rating: 75V
R48 R49 R52 R56 = CMP-009-00190-2: Res Thick Film 0603 1K Ohm 1% 1/10W ±100ppm/°C Molded SMD Punched Carrier T/R; Voltage Rating: 75V; Power: 100mW
R64 = CMP-RES-00066-1: Res Thin Film 0603 6.2K Ohm 0.1% 1/10W ±25ppm/°C Molded SMD SMD Punched Carrier T/R; Max Power Dissipation: 100mW; Voltage Rating: 75V
R181 = CMP-RES-00069-1: SMD Chip Resistor, 100 Ohm, ± 1%, 500 mW, 0805 [2012 Metric], Thick Film, Anti-Surge; Temperature Coefficient: 100ppm/°C; Voltage Rating: 150V
TP9 TP12 TP13 TP15 TP16 = NOBOM-00007: Test point, TH, 0.78mm (30mil) hole, 1.27mm (50 mil) pad; manufacturer: New Horizons; id: 137437
U1 = CMP-ICANA-00000-1: Quad low-power industrial grade standard comparator 14-SOIC -40 to 85; Min Supply Voltage: 3V; Max Supply Voltage: 30V
U2 = CMP-ICPWR-00000-1: V-Ref Adjustable 1.24V to 24V 100mA 3-Pin SOT-23 T/R; Max Supply Voltage: 25V; Tolerance: 0.25%
U3 = CMP-ICANA-00001-1: Micropower CMOS dual voltage comparator, 9µA, 16V, -40, 0 to 125, 70°C, SO-8, Tape and Reel; Min Supply Voltage: 2.7V
U4 = CMP-ICANA-00002-2: Op Amp Single Low Power Amplifier R-R I/O ±8V/16V 5-Pin SOT-23 T/R; Bandwidth: 5.5kHz; Max Supply Voltage: 16V; Min Supply Voltage: 2.5V

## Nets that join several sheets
Vcoil: PowerHV (K1.PLUS), Protect (11 pins)
LFUSED: PowerHV (F1.1 K1.NO RV1.2 RV3.1), Protect (C5.1 R2.1 R3.1 R10.1)
NEUT: PowerHV (8 pins), Protect (D6.AC2)
PROT_RESET: PowerHV (K1.RESET), Protect (D1.A Q2.3)
PROT_SET: PowerHV (K1.SET), Protect (D2.A Q3.3)

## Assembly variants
As Built: not fitted C1 J3 J4 J5 J6 J7 J8 J9 L1 R23 R28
